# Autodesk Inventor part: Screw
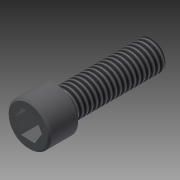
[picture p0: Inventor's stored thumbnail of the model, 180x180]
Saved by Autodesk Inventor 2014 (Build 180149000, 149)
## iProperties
Created: 2006-07
Part Number: Screw
Material: system_material_0
Description: SCREW, CAP, 1/4-20 X 3/8
Document SubType Name: Modeling
Designer: Z.MCGILL
Engineer: SAP
Manufacturer: Standard
Standards Organization: Custom
Mass: 26.2447 g
Surface Area: 18.9522 cm^2
Volume: 3.34682 cm^3
Density: 7.84168 g/cm^3
Appearance: system_RenderingStyle_0
NetWeight: 0.005
WeightUOM: KG
ModelCode: Comp
Author: Z.MCGILL
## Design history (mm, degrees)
node "SHCS"
body "Solid1"
tag "TaggingFeature2"
feature "DerivedBody::SHCS"
other parameters: "Thread_Length" = 31.75, "Head_Chamfer" = 0.635, "Thread_Chamfer" = 0.2286, "Thread_Diameter" = 9.525, "Head_Diameter" = 14.2875, "Head_Length" = 9.525, "Hex_Head_Width" = 7.9375, "Hex_Head_Depth" = 7.9375, "d23" = 0, "d24" = 0
